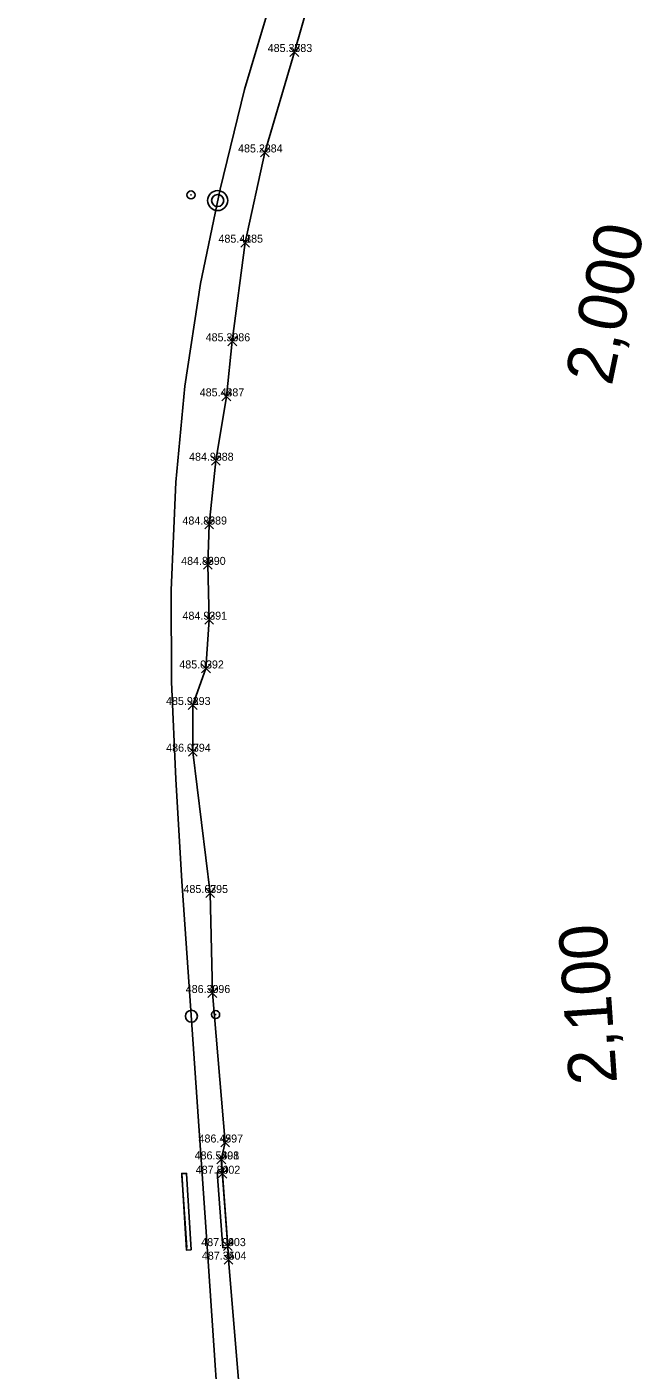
# Model space of a CAD drawing. Extents: x -874058 to -854960, y -10531873 to -1049126.
# Drawn here: x -867758.3 to -867681.4, y -1052445 to -1052277.2 of the extents above; entities that cross this region are included whole.
import ezdxf

# ---------------------------------------------------------------- set-up
doc = ezdxf.new("R2010")
doc.units = 0
for name, color, linetype in [('Vrstva 1', 7, 'Continuous'), ('Vrstva 17', 7, 'Continuous'), ('Vrstva 18', 7, 'Continuous'), ('Vrstva 32', 7, 'Continuous'), ('Vrstva 4', 7, 'Continuous'), ('Vrstva 60', 7, 'Continuous'), ('Vrstva 61', 7, 'Continuous'), ('Vrstva 7', 7, 'Continuous')]:
    doc.layers.add(name, color=color, linetype=linetype)

msp = doc.modelspace()

# ---------------------------------------------------------------- linework, layer by layer
at = {"layer": 'Vrstva 1'}
for points in [[(-867727.71, -1052273.38), (-867731.17, -1052284.97), (-867734.21, -1052297.44), (-867736.67, -1052309.21), (-867738.62, -1052322.03), (-867739.72, -1052334.02), (-867740.32, -1052347.54), (-867740.27, -1052358.97), (-867739.74, -1052371.15), (-867738.97, -1052383.9), (-867737.8, -1052400.63)], [(-867758.34, -1052953.41), (-867752.55, -1052918.31), (-867745.6, -1052876.96), (-867740.12, -1052843.52), (-867734.78, -1052811.15), (-867727.06, -1052764.8), (-867725.28, -1052752.68), (-867722.96, -1052735.8), (-867721.69, -1052722.71), (-867720.41, -1052707.04), (-867719.89, -1052691.86), (-867719.59, -1052676.18), (-867719.9, -1052663.05), (-867720.43, -1052649.3), (-867721.47, -1052632.86), (-867723.9, -1052600.11), (-867726.2, -1052566.58), (-867728.57, -1052532.52), (-867731.17, -1052495.79), (-867733.65, -1052461.64), (-867735.85, -1052428.9), (-867737.8, -1052400.63)]]:
    msp.add_lwpolyline(points, dxfattribs=at)
at = {"layer": 'Vrstva 17'}
for points in [[(-867738.97, -1052420.63), (-867738.38, -1052429.65)], [(-867733.23, -1052429.47), (-867733.92, -1052420.43)]]:
    msp.add_lwpolyline(points, dxfattribs=at)
at = {"layer": 'Vrstva 18'}
for points in [[(-867737.83, -1052429.92), (-867738.39, -1052420.38), (-867738.99, -1052420.39), (-867738.39, -1052429.98), (-867737.83, -1052429.92)], [(-867733.85, -1052429.69), (-867733.26, -1052429.66), (-867733.95, -1052420.14), (-867734.56, -1052420.24), (-867733.85, -1052429.69)]]:
    msp.add_lwpolyline(points, dxfattribs=at)
at = {"layer": 'Vrstva 32'}
for points in [[(-867734.06, -1052418.64), (-867733.57, -1052416.53), (-867735.17, -1052397.85), (-867735.45, -1052385.36), (-867737.61, -1052367.71), (-867737.63, -1052361.87), (-867735.97, -1052357.31), (-867735.57, -1052351.22), (-867735.74, -1052344.37), (-867735.58, -1052339.33), (-867734.75, -1052331.36), (-867733.42, -1052323.32), (-867732.68, -1052316.44), (-867731.08, -1052304.12), (-867728.63, -1052292.85), (-867724.93, -1052280.3), (-867723.26, -1052274.49)], [(-867734.06, -1052418.64), (-867733.92, -1052420.43), (-867733.23, -1052429.47), (-867733.15, -1052431.16)], [(-867728.87, -1052482.68), (-867733.15, -1052431.16)]]:
    msp.add_lwpolyline(points, dxfattribs=at)
at = {"layer": 'Vrstva 4'}
msp.add_lwpolyline([(-867733.15, -1052431.16), (-867733.26, -1052429.66), (-867733.92, -1052420.43), (-867734.04, -1052418.64)], dxfattribs=at)
at = {"layer": 'Vrstva 60'}
for p, q in [((-867725.48, -1052280.85), (-867724.38, -1052279.75)), ((-867724.38, -1052280.85), (-867725.48, -1052279.75)), ((-867729.18, -1052293.4), (-867728.08, -1052292.3)), ((-867728.08, -1052293.4), (-867729.18, -1052292.3)), ((-867731.63, -1052304.67), (-867730.53, -1052303.57)), ((-867730.53, -1052304.67), (-867731.63, -1052303.57)), ((-867733.23, -1052316.99), (-867732.13, -1052315.89)), ((-867732.13, -1052316.99), (-867733.23, -1052315.89)), ((-867733.97, -1052323.87), (-867732.87, -1052322.77)), ((-867732.87, -1052323.87), (-867733.97, -1052322.77)), ((-867735.3, -1052331.91), (-867734.2, -1052330.81)), ((-867734.2, -1052331.91), (-867735.3, -1052330.81)), ((-867736.13, -1052339.88), (-867735.03, -1052338.78)), ((-867735.03, -1052339.88), (-867736.13, -1052338.78)), ((-867736.29, -1052344.92), (-867735.19, -1052343.82)), ((-867735.19, -1052344.92), (-867736.29, -1052343.82)), ((-867736.12, -1052351.77), (-867735.02, -1052350.67)), ((-867735.02, -1052351.77), (-867736.12, -1052350.67)), ((-867736.52, -1052357.86), (-867735.42, -1052356.76)), ((-867735.42, -1052357.86), (-867736.52, -1052356.76)), ((-867738.18, -1052362.42), (-867737.08, -1052361.32)), ((-867737.08, -1052362.42), (-867738.18, -1052361.32)), ((-867738.16, -1052368.26), (-867737.06, -1052367.16)), ((-867737.06, -1052368.26), (-867738.16, -1052367.16)), ((-867736, -1052385.91), (-867734.9, -1052384.81)), ((-867734.9, -1052385.91), (-867736, -1052384.81)), ((-867735.72, -1052398.4), (-867734.62, -1052397.3)), ((-867734.62, -1052398.4), (-867735.72, -1052397.3)), ((-867734.12, -1052417.08), (-867733.02, -1052415.98)), ((-867733.02, -1052417.08), (-867734.12, -1052415.98)), ((-867734.61, -1052419.19), (-867733.51, -1052418.09)), ((-867733.51, -1052419.19), (-867734.61, -1052418.09)), ((-867734.61, -1052419.19), (-867733.51, -1052418.09)), ((-867733.51, -1052419.19), (-867734.61, -1052418.09)), ((-867734.47, -1052420.98), (-867733.37, -1052419.88)), ((-867733.37, -1052420.98), (-867734.47, -1052419.88)), ((-867733.78, -1052430.02), (-867732.68, -1052428.92)), ((-867732.68, -1052430.02), (-867733.78, -1052428.92)), ((-867733.7, -1052431.71), (-867732.6, -1052430.61)), ((-867732.6, -1052431.71), (-867733.7, -1052430.61))]:
    msp.add_line(p, q, dxfattribs=at)
at = {"layer": 'Vrstva 7'}
for p, q in [((-867737.89, -1052298.16), (-867737.79, -1052298.16)), ((-867734.81, -1052400.54), (-867734.71, -1052400.54))]:
    msp.add_line(p, q, dxfattribs=at)
for centre, radius in [((-867737.84, -1052298.16), 0.5), ((-867734.51, -1052298.86), 1.25), ((-867734.51, -1052298.86), 0.752), ((-867737.79, -1052400.75), 0.75), ((-867734.76, -1052400.54), 0.5)]:
    msp.add_circle(centre, radius, dxfattribs=at)

# ---------------------------------------------------------------- texts
at = {"layer": 'Vrstva 60'}
for s, p in [('383', (-867724.93, -1052280.3)), ('384', (-867728.63, -1052292.85)), ('385', (-867731.08, -1052304.12)), ('386', (-867732.68, -1052316.44)), ('387', (-867733.42, -1052323.32)), ('388', (-867734.75, -1052331.36)), ('389', (-867735.58, -1052339.33)), ('390', (-867735.74, -1052344.37)), ('391', (-867735.57, -1052351.22)), ('392', (-867735.97, -1052357.31)), ('393', (-867737.63, -1052361.87)), ('394', (-867737.61, -1052367.71)), ('395', (-867735.45, -1052385.36)), ('396', (-867735.17, -1052397.85)), ('397', (-867733.57, -1052416.53)), ('401', (-867734.06, -1052418.64)), ('398', (-867734.06, -1052418.64)), ('402', (-867733.92, -1052420.43)), ('403', (-867733.23, -1052429.47)), ('404', (-867733.15, -1052431.16))]:
    msp.add_text(s, height=1, dxfattribs=at).set_placement(p)
at = {"layer": 'Vrstva 61'}
for s, p in [('485.37 ', (-867728.26, -1052280.3)), ('485.28 ', (-867731.96, -1052292.85)), ('485.41 ', (-867734.41, -1052304.12)), ('485.30 ', (-867736.01, -1052316.44)), ('485.44 ', (-867736.75, -1052323.32)), ('484.96 ', (-867738.08, -1052331.36)), ('484.86 ', (-867738.91, -1052339.33)), ('484.86 ', (-867739.07, -1052344.37)), ('484.93 ', (-867738.9, -1052351.22)), ('485.03 ', (-867739.3, -1052357.31)), ('485.91 ', (-867740.96, -1052361.87)), ('486.07 ', (-867740.94, -1052367.71)), ('485.67 ', (-867738.78, -1052385.36)), ('486.30 ', (-867738.5, -1052397.85)), ('486.45 ', (-867736.9, -1052416.53)), ('486.56 ', (-867737.39, -1052418.64)), ('486.56 ', (-867737.39, -1052418.64)), ('487.80 ', (-867737.25, -1052420.43)), ('487.99 ', (-867736.56, -1052429.47)), ('487.35 ', (-867736.48, -1052431.16))]:
    msp.add_text(s, height=1, dxfattribs=at).set_placement(p)
at = {"layer": 'Vrstva 7'}
for s, rotation, p in [('2,000', 78.1947, (-867685.3, -1052322.12)), ('2,100', 93.9459, (-867684.61, -1052409.09))]:
    msp.add_text(s, height=6, rotation=rotation, dxfattribs=at).set_placement(p)

doc.saveas('drawing.dxf')
